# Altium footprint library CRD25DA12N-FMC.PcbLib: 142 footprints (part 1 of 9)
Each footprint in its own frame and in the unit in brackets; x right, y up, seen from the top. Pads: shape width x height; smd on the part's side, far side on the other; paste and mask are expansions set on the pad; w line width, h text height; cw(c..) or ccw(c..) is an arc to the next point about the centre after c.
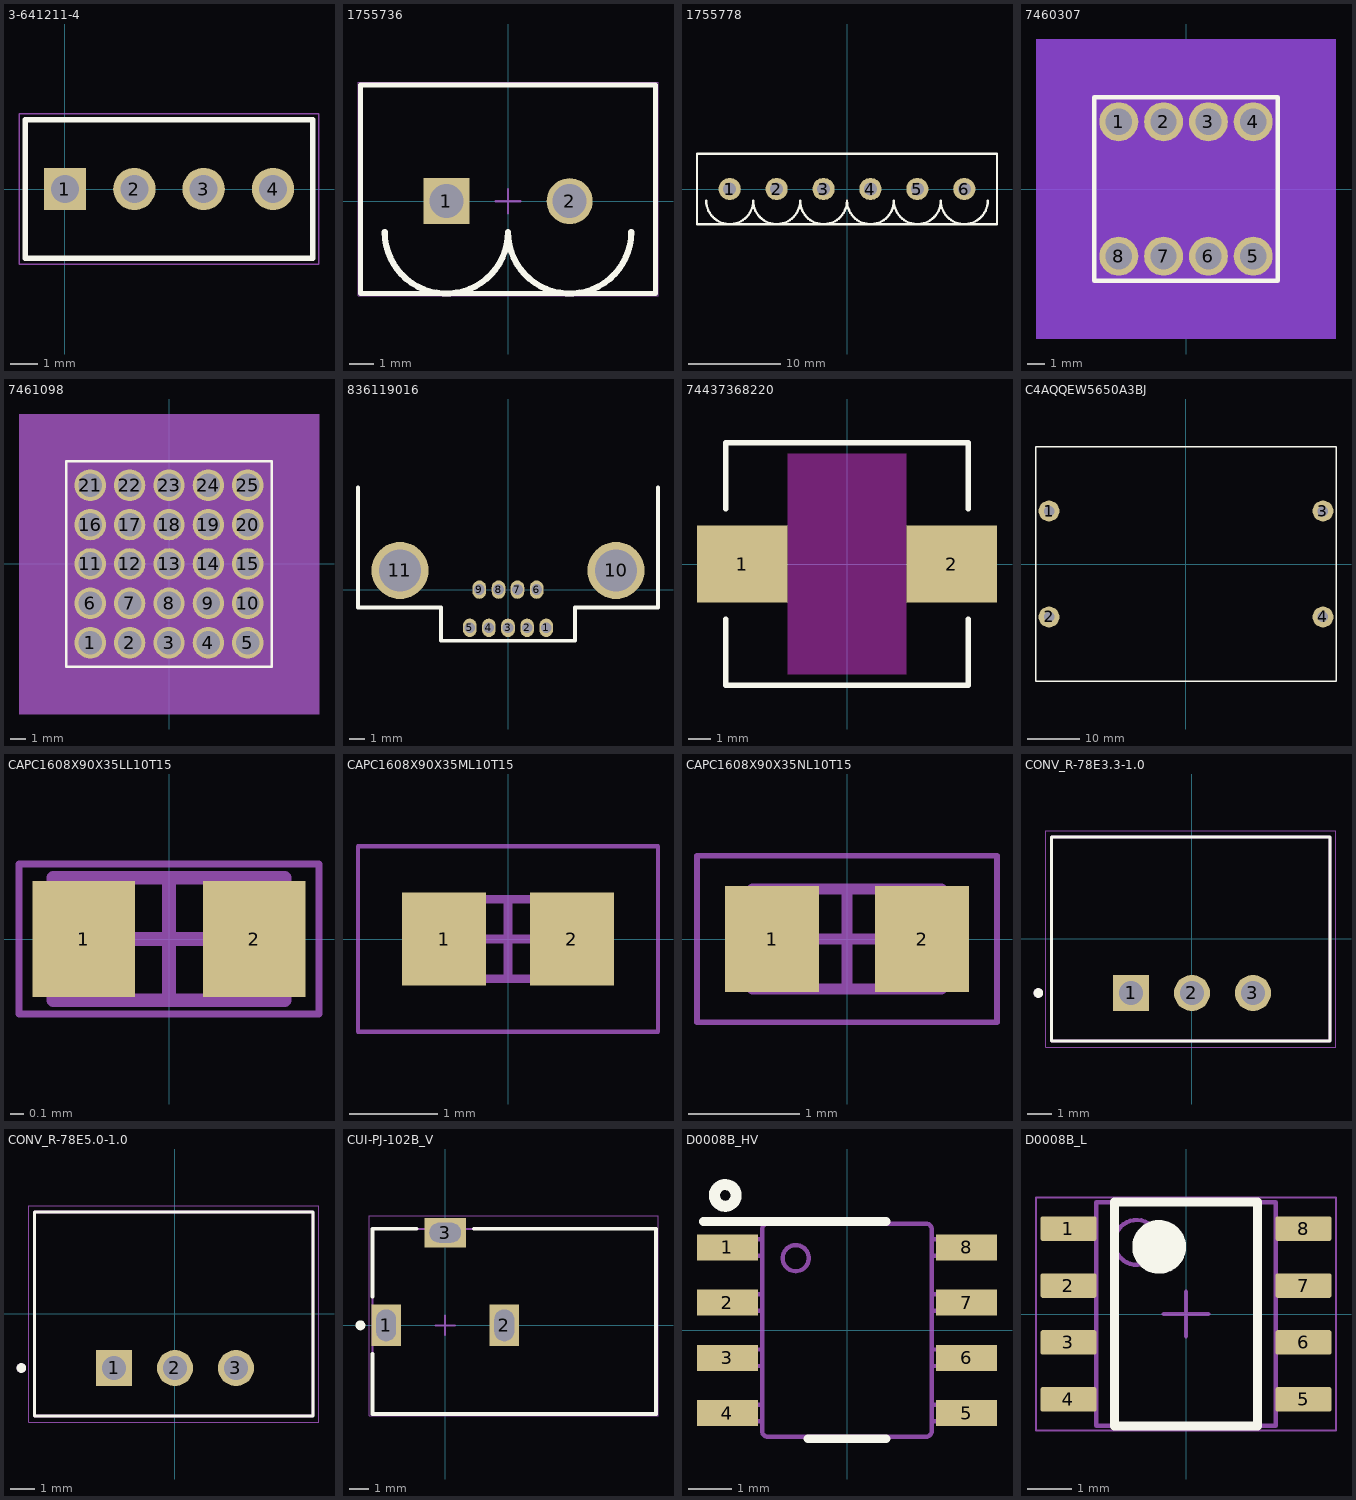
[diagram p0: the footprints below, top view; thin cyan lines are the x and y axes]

## 3-641211-4 [mm] "Connector Header Through Hole 4 position 0.100\" (2.54mm)"
height 10.03
pads (4):
  rect 1.55x1.55 hole 1.02: 1(0,0)
  round 1.55 hole 1.02: 2(2.54,0) 3(5.08,0) 4(7.62,0)
Top Overlay:
  lines w0.2: -1.46,-2.54 -1.46,2.54 9.08,2.54 9.08,-2.54 -1.46,-2.54
Mechanical 13:
  lines w0.1: -1.46,-2.54 -1.46,2.54 9.08,2.54 9.08,-2.54 -1.46,-2.54
Mechanical 15:
  lines w0.05: -1.685,-2.765 -1.685,2.765 9.305,2.765 9.305,-2.765 -1.685,-2.765
3D body "TE 3-641211-4 Color.STEP": height 10.09, standoff -3.5, extent -1.28,-2.54 8.88,2.54

## 1755736 [mm] "THD, 2-Leads, Body 12.16x8.6mm, Pitch 5.08mm"
height 12
pads (2):
  rect 1.9x1.9 hole 1.4: 1(-2.54,0)
  round 1.9 hole 1.4: 2(2.54,0)
Top Overlay:
  lines w0.2: -6.08,-3.81 -6.08,4.79 6.08,4.79 6.08,-3.81 -6.08,-3.81
  lines w0.254: -5.08,-1.27 ccw(c-2.54,-1.27) 0,-1.27 ccw(c2.54,-1.27) 5.08,-1.27
Mechanical 13:
  lines w0.1: -6.08,-3.8 6.08,-3.8 6.08,4.8 -6.08,4.8 -6.08,-3.8
Mechanical 15:
  lines w0.05: -6.18,-3.9 -6.18,4.9 6.18,4.9 6.18,-3.9 -6.18,-3.9
  lines w0.1: -0.5,0 0.5,0 ; 0,-0.5 0,0.5
3D body: height 10, standoff -3.9, extent -3.04,-0.499 -2.044,0.499
3D body: height 10, standoff -3.9, extent 2.04,-0.499 3.036,0.499
3D body: height 12, standoff 4, extent -6.079,-3.799 6.079,4.799
3D body "Phoenix Contact 1755736.stp": height 12, standoff -3.9, extent -6,-3.7 6.16,4.87

## 1755778 [mm] "TERM BLOCK HDR 6POS VERT 5.08MM"
pads (6):
  round 2.4 hole 1.4: 1(-12.7,0) 2(-7.62,0) 3(-2.54,0) 4(2.54,0) 5(7.62,0) 6(12.7,0)
Top Overlay:
  lines w0.254: -15.24,-1.27 ccw(c-12.7,-1.27) -10.16,-1.27 ccw(c-7.62,-1.27) -5.08,-1.27 ccw(c-2.54,-1.27) 0,-1.27 ccw(c2.54,-1.27) 5.08,-1.27 ccw(c7.62,-1.27) 10.16,-1.27 ccw(c12.7,-1.27) 15.24,-1.27 ; -16.24,-3.835 16.24,-3.835 16.24,3.835 -16.24,3.835 -16.24,-3.835
3D body "Phoenix Contact 1755778.stp": height 12, standoff -3.9, extent -16.24,-3.835 16.24,4.765

## 7460307 [mm] "8 Pin Screw Terminal, Power Tap M4 Through Hole"
pads (8):
  round 2.21 hole 1.475: 1(-3.81,3.81) 2(-1.27,3.81) 3(1.27,3.81) 4(3.81,3.81) 5(3.81,-3.81) 6(1.27,-3.81) 7(-1.27,-3.81) 8(-3.81,-3.81)
Top Layer keep-out:
  rectangle: -8.5,-8.5 8.5,8.5
Bottom Layer keep-out:
  rectangle: -8.5,-8.5 8.5,8.5
Top Overlay:
  lines w0.254: -5.2,-5.2 -5.2,5.2 5.2,5.2 5.2,-5.2 -5.2,-5.2
3D body "Wurth 7460307 - Modified.STEP": height 7, standoff -3.5, extent -4.5,-4.5 4.5,4.5

## 7461098 [mil]
pads (25):
  round 80 hole 60 mask+0: 1(-200,-200) 2(-100,-200) 3(0,-200) 4(100,-200) 5(200,-200) 6(-200,-100) 7(-100,-100) 8(0,-100) 9(100,-100) 10(200,-100) 11(-200,0) 12(-100,0) 13(0,0) 14(100,0) 15(200,0) 16(-200,100) 17(-100,100) 18(0,100) 19(100,100) 20(200,100) 21(-200,200) 22(-100,200) 23(0,200) 24(100,200) 25(200,200)
Top Overlay:
  lines w6: -261,-261.09 261,-261.09 261,260.91 -261,260.91 -261,-261.09
Mechanical 5:
  region: -381,380.91 381,380.91 381,-381.09 -381,-381.09
Mechanical 13:
  lines w1: -256,-256.09 256,-256.09 256,255.91 -256,255.91 -256,-256.09
Mechanical 15:
  region: 266,265.91 -266,265.91 -266,-266.09 266,-266.09
  lines w6: -266,-266.09 -266,265.91 266,265.91 266,-266.09 -266,-266.09
3D body: height 10, standoff 0, extent -200,-200 -190,-190
3D body "7461098_Download_STP_7461098_rev1.stp": height 610.24, standoff -137.8, extent -255.91,-255.91 255.91,255.91

## 836119016 [mm]
pads (11):
  oval 0.91x1.218 hole 0.71: 1(2.54,-2.54) 2(1.27,-2.54) 3(0,-2.54) 4(-1.27,-2.54) 5(-2.54,-2.54) 6(1.905,0) 7(0.625,0) 8(-0.625,0) 9(-1.905,0)
  round 3.79 hole 2.79: 10(7.175,1.27) 11(-7.175,1.27)
Top Overlay:
  lines w0.254: -9.965,6.8 -9.965,-1.2 -4.46,-1.2 -4.46,-3.4 4.46,-3.4 4.46,-1.2 9.965,-1.2 9.965,6.8
3D body "Molex 836119016 Color.STEP": height 7.99, standoff -2.61, extent -9.938,-3.491 9.912,11.419

## 74437368220 [mm]
pads (2):
  rect 4.1x3.5 smd: 1(-4.75,0) 2(4.75,0)
Top Layer keep-out:
  rectangle: -2.7,-5 2.7,5
Top Overlay:
  lines w0.254: -5.5,-2.5 -5.5,-5.5 5.5,-5.5 5.5,-2.5 ; -5.5,2.5 -5.5,5.5 5.5,5.5 5.5,2.5
Top Solder:
  rectangle: -2.7,-5.6 2.7,5.6
3D body "WE-LHMI_1040 (rev1).stp": height 3.7, standoff -0.1, extent -5.5,-5 5.5,5

## C4AQQEW5650A3BJ [mm] "CAP FILM 65UF 5% 1.1KVDC RAD"
pads (4):
  round 4 hole 2: 1(-26.25,10.15) 2(-26.25,-10.15) 3(26.25,10.15) 4(26.25,-10.15)
Top Overlay:
  lines w0.254: -28.75,-22.5 28.75,-22.5 28.75,22.5 -28.75,22.5 -28.75,-22.5
3D body "Kemet C4AQQEW5650A3BJ.step": height 65.4, standoff -5.9, extent -29.15,-22.755 29.15,22.75

## CAPC1608X90X35LL10T15 [mm] "Chip Capacitor, 2-Leads, Body 1.60x0.80mm, IPC High Density"
height 0.9
pads (2):
  rect 0.75x0.85 smd: 1(-0.625,0) 2(0.625,0)
Mechanical 13:
  lines w0.1: -0.85,-0.45 -0.85,0.45 0.85,0.45 0.85,-0.45 -0.85,-0.45
Mechanical 15:
  lines w0.05: -1.1,-0.55 -1.1,0.55 1.1,0.55 1.1,-0.55 -1.1,-0.55
  lines w0.1: -0.45,0 0.45,0 ; 0,-0.45 0,0.45
3D body: height 0.9, standoff 0, extent -0.5,-0.45 0.5,0.45
3D body: height 0.9, standoff 0, extent -0.85,-0.45 -0.5,0.45
3D body: height 0.9, standoff 0, extent 0.5,-0.45 0.85,0.45

## CAPC1608X90X35ML10T15 [mm] "Chip Capacitor, 2-Leads, Body 1.60x0.80mm, IPC Low Density"
height 0.9
pads (2):
  rect 0.95x1.05 smd: 1(-0.725,0) 2(0.725,0)
Mechanical 13:
  lines w0.1: -0.85,-0.45 0.85,-0.45 0.85,0.45 -0.85,0.45 -0.85,-0.45
Mechanical 15:
  lines w0.05: -1.7,-1.05 1.7,-1.05 1.7,1.05 -1.7,1.05 -1.7,-1.05
  lines w0.1: -0.45,0 0.45,0 ; 0,-0.45 0,0.45
3D body: height 0.9, standoff 0, extent 0.5,-0.45 0.85,0.45
3D body: height 0.9, standoff 0, extent -0.85,-0.45 -0.5,0.45
3D body: height 0.9, standoff 0, extent -0.5,-0.45 0.5,0.45

## CAPC1608X90X35NL10T15 [mm] "Chip Capacitor, 2-Leads, Body 1.60x0.80mm, IPC Medium Density"
height 0.9
pads (2):
  rect 0.85x0.95 smd: 1(-0.675,0) 2(0.675,0)
Mechanical 13:
  lines w0.1: -0.85,-0.45 0.85,-0.45 0.85,0.45 -0.85,0.45 -0.85,-0.45
Mechanical 15:
  lines w0.05: -1.35,-0.75 1.35,-0.75 1.35,0.75 -1.35,0.75 -1.35,-0.75
  lines w0.1: -0.45,0 0.45,0 ; 0,-0.45 0,0.45
3D body: height 0.9, standoff 0, extent 0.5,-0.45 0.85,0.45
3D body: height 0.9, standoff 0, extent -0.85,-0.45 -0.5,0.45
3D body: height 0.9, standoff 0, extent -0.5,-0.45 0.5,0.45

## CONV_R-78E3.3-1.0 [mm]
pads (3):
  rect 1.508x1.508 hole 1: 1(-2.54,-2.25)
  round 1.508 hole 1: 2(0,-2.25) 3(2.54,-2.25)
Top Overlay:
  circle w0.2: c-6.4,-2.25 r0.1
  lines w0.127: -5.85,-4.25 -5.85,4.25 5.75,4.25 5.75,-4.25 -5.85,-4.25
Top Designator:
  text ".Designator" at 7.33,0.508 h1.52
Mechanical 13:
  circle w0.2: c-6.4,-2.25 r0.1
  lines w0.127: -5.85,-4.25 -5.85,4.25 5.75,4.25 5.75,-4.25 -5.85,-4.25
Mechanical 15:
  lines w0.05: -6.1,-4.5 -6.1,4.5 6,4.5 6,-4.5 -6.1,-4.5
3D body "step_temp.STEP": height 9.9, standoff -4.6, extent -5.8,-4.25 5.8,4.25

## CONV_R-78E5.0-1.0 [mm]
pads (3):
  rect 1.508x1.508 hole 1: 1(-2.54,-2.25)
  round 1.508 hole 1: 2(0,-2.25) 3(2.54,-2.25)
Top Overlay:
  circle w0.2: c-6.4,-2.25 r0.1
  lines w0.127: -5.85,-4.25 -5.85,4.25 5.75,4.25 5.75,-4.25 -5.85,-4.25
Top Designator:
  text ".Designator" at 7.33,0.508 h1.52
Mechanical 13:
  circle w0.2: c-6.4,-2.25 r0.1
  lines w0.127: -5.85,-4.25 -5.85,4.25 5.75,4.25 5.75,-4.25 -5.85,-4.25
Mechanical 15:
  lines w0.05: -6.1,-4.5 -6.1,4.5 6,4.5 6,-4.5 -6.1,-4.5
3D body "step_temp.STEP": height 9.9, standoff -4.6, extent -5.8,-4.25 5.8,4.25

## CUI-PJ-102B_V [mm] "THD, 3-Leads, Body 14.4x9mm, Height 11mm"
height 11
pads (3):
  rect 1.5x2.1 hole 1 slot 1.6 at 90 deg: 1(-3,0) 2(3,0)
  rect 2.1x1.5 hole 1 slot 1.6 at 0 deg: 3(0,4.7)
Top Overlay:
  circle w0.25: c-4.3,0 r0.125
  lines w0.2: -3.7,-1.45 -3.7,-4.5 10.7,-4.5 10.7,4.9 1.45,4.9 ; -3.7,1.45 -3.7,4.9 -1.45,4.9
Mechanical 13:
  lines w0.1: -3.7,-4.5 10.7,-4.5 10.7,4.9 -3.7,4.9 -3.7,-4.5
Mechanical 15:
  lines w0.05: -3.85,-4.6 10.8,-4.6 10.8,5.55 -3.85,5.55 -3.85,-4.6
  lines w0.1: -0.5,0 0.5,0 ; 0,-0.5 0,0.5
3D body "pj-102b.stp": height 11, standoff -3.5, extent -3.7,-4.5 10.7,4.9

## D0008B_HV [mm]
pads (8):
  rect 1.4x0.6 smd paste+0 mask+0: 1(-2.75,1.905) 2(-2.75,0.635) 3(-2.75,-0.635) 4(-2.75,-1.905) 5(2.75,-1.905) 6(2.75,-0.635) 7(2.75,0.635) 8(2.75,1.905)
Top Overlay:
  circle w0.254: c-2.8,3.1 r0.25
  lines w0.2: -3.3,2.5 0.9,2.5 ; -0.9,-2.5 0.9,-2.5
Mechanical 13:
  lines w0.1: -2.375,-2.095 -1.995,-2.095 -1.952,-2.095 -1.952,-1.715 -1.995,-1.715 -2.375,-1.715 ; -2.375,-2.095 -2.589,-2.095 -3.002,-2.095 -3.002,-1.715 -2.589,-1.715 -2.375,-1.715 ; -2.375,-2.095 -2.375,-1.715 ; -2.375,-0.825 -1.995,-0.825 -1.952,-0.825 -1.952,-0.445 -1.995,-0.445 -2.375,-0.445 ; -2.375,-0.825 -2.589,-0.825 -3.002,-0.825 -3.002,-0.445 -2.589,-0.445 -2.375,-0.445 ; -2.375,-0.825 -2.375,-0.445 ; -2.375,0.445 -1.995,0.445 -1.952,0.445 -1.952,0.825 -1.995,0.825 -2.375,0.825 ; -2.375,0.445 -2.589,0.445 -3.002,0.445 -3.002,0.825 -2.589,0.825 -2.375,0.825 ; -2.375,0.445 -2.375,0.825 ; -2.375,1.715 -1.995,1.715 -1.952,1.715 -1.952,2.095 -1.995,2.095 -2.375,2.095 ; -2.375,1.715 -2.589,1.715 -3.002,1.715 -3.002,2.095 -2.589,2.095 -2.375,2.095 ; -2.375,1.715 -2.375,2.095 ; -0.332,-2.45 -1.825,-2.45 -1.826,-2.45 cw(c-1.825,-2.323) -1.952,-2.324 -1.952,-2.323 -1.952,2.323 -1.952,2.324 cw(c-1.825,2.323) -1.826,2.45 -1.825,2.45 -0.332,2.45 ; -0.332,-2.45 -0.182,-2.45 ; -0.332,-2.45 -0.182,-2.45 ; -0.332,2.45 -0.182,2.45 ; -0.332,2.45 -0.182,2.45 ; -0.182,-2.45 0.178,-2.45 ; -0.182,2.45 0.178,2.45 ; 0.178,-2.45 0.328,-2.45 ; 0.178,-2.45 0.328,-2.45 ; 0.178,2.45 0.328,2.45 ; 0.178,2.45 0.328,2.45 ; 0.328,-2.45 1.821,-2.45 1.822,-2.45 ccw(c1.821,-2.323) 1.948,-2.324 1.948,-2.323 1.948,2.323 1.948,2.324 ccw(c1.821,2.323) 1.822,2.45 1.821,2.45 0.328,2.45 ; 2.371,-2.095 2.585,-2.095 2.998,-2.095 2.998,-1.715 2.585,-1.715 2.371,-1.715 ; 2.371,-2.095 1.991,-2.095 1.948,-2.095 1.948,-1.715 1.991,-1.715 2.371,-1.715 ; 2.371,-2.095 2.371,-1.715 ; 2.371,-0.825 2.585,-0.825 2.998,-0.825 2.998,-0.445 2.585,-0.445 2.371,-0.445 ; 2.371,-0.825 1.991,-0.825 1.948,-0.825 1.948,-0.445 1.991,-0.445 2.371,-0.445 ; 2.371,-0.825 2.371,-0.445 ; 2.371,0.445 2.585,0.445 2.998,0.445 2.998,0.825 2.585,0.825 2.371,0.825 ; 2.371,0.445 1.991,0.445 1.948,0.445 1.948,0.825 1.991,0.825 2.371,0.825 ; 2.371,0.445 2.371,0.825 ; 2.371,1.715 2.585,1.715 2.998,1.715 2.998,2.095 2.585,2.095 2.371,2.095 ; 2.371,1.715 1.991,1.715 1.948,1.715 1.948,2.095 1.991,2.095 2.371,2.095 ; 2.371,1.715 2.371,2.095 ; -1.18,1.356 cw(c-1.18,1.656) -1.18,1.956 cw(c-1.18,1.656) -1.18,1.356
3D body: height 0.25, standoff 0, extent 0,0 0.254,0.254
3D body "D0008B.stp": height 1.63, standoff 0, extent -3.011,-2.451 3.011,2.451

## D0008B_L [mm] "SOIC, 8-Leads, Body 5x4mm, Pitch 1.27mm, IPC High Density"
height 1.75
pads (8):
  rrect18% 1.25x0.55 smd: 1(-2.625,1.905) 2(-2.625,0.635) 3(-2.625,-0.635) 4(-2.625,-1.905) 5(2.625,-1.905) 6(2.625,-0.635) 7(2.625,0.635) 8(2.625,1.905)
Top Overlay:
  circle w0.6: c-0.6,1.5 r0.3
  lines w0.2: -1.6,-2.5 -1.6,2.5 1.6,2.5 1.6,-2.5 -1.6,-2.5
Mechanical 1:
  text ".Designator" at -1.397,-0.254 h0.6
Mechanical 13:
  circle w0.1: c-1.1,1.6 r0.5
  lines w0.1: -2,-2.5 -2,2.5 2,2.5 2,-2.5 -2,-2.5
Mechanical 15:
  lines w0.05: -3.35,-2.6 -3.35,2.6 3.35,2.6 3.35,-2.6 -3.35,-2.6
  lines w0.1: -0.5,0 0.5,0 ; 0,-0.5 0,0.5
3D body "SOIC-8akaD0008AakaM08A.stp": height 1.63, standoff 0, extent -3,-2.45 3,2.45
